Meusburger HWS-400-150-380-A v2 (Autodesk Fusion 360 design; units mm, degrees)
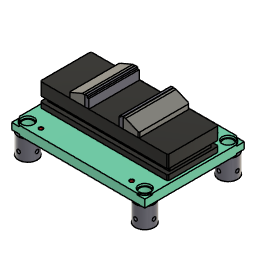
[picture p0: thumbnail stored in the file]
parameter "Ouverture" = 100
base_feature "Base Feature1" OffsetX 0 OffsetY 0 OffsetZ 0 OffsetX 0 OffsetY 0 OffsetZ 0 OffsetX 0 OffsetY 0 OffsetZ 0
base_feature "Base Feature1"
base_feature "Base Feature1" OffsetX 0 OffsetY 0 OffsetZ 0
base_feature "Base Feature1"
base_feature "Base Feature1" OffsetX 0 OffsetY 0 OffsetZ 0 OffsetX 0 OffsetY 0 OffsetZ 0
as_built_joint "As-built1"
as_built_joint "As-built1"
joint "Assemble1" alignOffsetX 0 alignOffsetY 0 alignOffsetZ 45 (= "Ouverture / 2 - 5 mm")
joint "Assemble2" alignOffsetX 0 alignOffsetY 0 alignOffsetZ -45 (= "-Ouverture / 2 + 5 mm")
base_feature "Base Feature1"
position "Position1"
base_feature "Fonction de base"
position "Position2"
rectangular_pattern "00000000-0000-0000-0000-000000000000" uSpaceDistance 348 vSpaceDistance 248
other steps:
create_component "CreateComponent1"
create_component "CreateComponent2"
create_component "CreateComponent1"
create_component "CreateComponent2"
create_component "CreateComponent3"
create_component "CreateComponent1"
create_component "CreateComponent2"
joint_origin "JointOrigin2" OffsetX 0 OffsetY 0 OffsetZ 0
joint_origin "JointOrigin4" OffsetX 0 OffsetY 0 OffsetZ 0
joint_origin "JointOrigin3" OffsetX 0 OffsetY 0 OffsetZ 0
joint_origin "JointOrigin5" OffsetX 0 OffsetY 0 OffsetZ 0
create_component "CreateComponent4"
create_component "CreateComponent5"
